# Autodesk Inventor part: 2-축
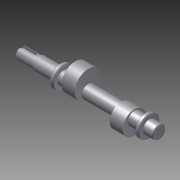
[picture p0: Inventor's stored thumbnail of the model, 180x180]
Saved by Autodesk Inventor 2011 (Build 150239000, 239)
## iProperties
Created: 2014-12
Part Number: 2-축
Document SubType Name: Modeling
Designer: user
Density: 1 g/cm^3
Author: user
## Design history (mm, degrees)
sketch "스케치1"
  geometry: L1 (-90, 0)-(90, 0); L2 (-90, 0)-(-90, 7.5); L3 (-90, 7.5)-(-66, 7.5); L4 (-66, 7.5)-(-66, 8.5); L5 (-66, 8.5)-(-39, 8.5); L6 (-39, 8.5)-(-39, 14); L7 (-39, 14)-(-34, 14); L8 (-34, 14)-(-34, 8.5); L9 (-34, 8.5)-(-27.139, 8.5); L10 (-27.139, 8.5)-(-27.139, 8.5); L11 (90, 8.5)-(90, 0); L12 (77, 8.5)-(77, 14); L13 (77, 14)-(72, 14); L14 (72, 14)-(72, 8.5); L15 (-27.139, 8.5)-(72, 8.5); L16 (77, 8.5)-(90, 8.5); 2 further points
  constraints: 32 end point, 11 parallel, 5 perpendicular, 1 coincident, 1 horizontal, 1 midpoint
  dimensions: "d0" = 180 distance of L1.start L1.end; "d1" = 15 diameter of L3 L1; "d2" = 17 diameter of L5 L1; "d3" = 28 diameter of L7 L1; "d4" = 24 distance of L2.end L3.end; "d5" = 27 distance of L4.end L5.end; "d6" = 5 distance of L6.end L7.end; "d8" = 17 diameter of L9 L1; "d9" = 17 diameter of L16 L1; "d10" = 17 diameter of L15 L1; "d11" = 28 diameter of L13 L1; "d12" = 5 distance of L12.end L13.end; "d13" = 13 distance between parallel lines of L11 L12
revolve "회전1" sketch "스케치1" stored, may be unused: angle "d14" = 90 deg
node "작업 평면1"
sketch "스케치2"
  geometry: C1 r 8.5 at (0, 0) reference; C2 r 17.5 at (-8, 0); 1 further point
  constraints: 1 centre point, 1 horizontal alignment
  dimensions: "d16" = 35 diameter of C2; "d17" = 8 distance of C2.centre point (0, 0)
extrude "돌출1" join sketch "스케치2" distance "d18" = 17; taper "d19" = 0 deg
node "작업 평면2"
sketch "스케치3"
  geometry: C1 r 8.5 at (0, 0) reference; C2 r 15 at (-5, 0); 1 further point
  constraints: 1 centre point, 1 horizontal alignment
  dimensions: "d21" = 30 diameter of C2; "d22" = 5 distance of C2.centre point (0, 0)
extrude "돌출2" join sketch "스케치3" distance "d23" = 17; taper "d24" = 0 deg
node "작업 평면3"
sketch "스케치4"
  geometry: L1 (-12, 0)-(12, 0) reference; L2 (12, -4)-(12, 0) reference; L3 (39, -4)-(12, -4) reference; L4 (39, -11.822)-(39, -4) reference; L5 (44, -11.822)-(39, -11.822) reference; L6 (44, -4)-(44, -11.822) reference; L7 (58.5, -4)-(44, -4) reference; L8 (58.5, -17.493)-(58.5, -4) reference; L9 (75.5, -17.493)-(58.5, -17.493) reference; L10 (75.5, -4)-(75.5, -17.493) reference; L11 (118.5, -4)-(75.5, -4) reference; L12 (118.5, -8.292)-(118.5, -4) reference; L13 (135.5, -8.292)-(118.5, -8.292) reference; L14 (135.5, -4)-(135.5, -8.292) reference; L15 (150, -4)-(135.5, -4) reference; L16 (150, -11.822)-(150, -4) reference; L17 (155, -11.822)-(150, -11.822) reference; L18 (155, -4)-(155, -11.822) reference; L19 (168, -4)-(155, -4) reference; L20 (168, 4)-(168, -4) reference; L21 (155, 4)-(168, 4) reference; L22 (155, 11.822)-(155, 4) reference; L23 (150, 11.822)-(155, 11.822) reference; L24 (150, 4)-(150, 11.822) reference; L25 (135.5, 4)-(150, 4) reference; L26 (135.5, 8.292)-(135.5, 4) reference; L27 (118.5, 8.292)-(135.5, 8.292) reference; L28 (118.5, 4)-(118.5, 8.292) reference; L29 (75.5, 4)-(118.5, 4) reference; L30 (75.5, 17.493)-(75.5, 4) reference; L31 (58.5, 17.493)-(75.5, 17.493) reference; L32 (58.5, 4)-(58.5, 17.493) reference; L33 (44, 4)-(58.5, 4) reference; L34 (44, 11.822)-(44, 4) reference; L35 (39, 11.822)-(44, 11.822) reference; L36 (39, 4)-(39, 11.822) reference; L37 (12, 4)-(39, 4) reference; L38 (12, 0)-(12, 4) reference; L39 (5.5, 2.5)-(-12, 2.5); L40 (-12, -7.5)-(-12, 7.5) reference; L41 (5.5, -2.5)-(-12, -2.5); A1 r 2.5 centre (5.5, 0) between (5.5, 2.5) and (5.5, -2.5); 2 further points
  constraints: 4 end point, 2 point on circle, 2 point on line, 2 tangent, 1 centre point, 1 horizontal alignment, 1 midpoint, 1 parallel, 1 perpendicular
  dimensions: "d25" = 5 diameter of A1; "d26" = 20 dimension on A1 L40
extrude "돌출3" cut sketch "스케치4" distance "d27" = 3; taper "d28" = 0 deg
chamfer "모따기1" distance "d29" = 1; stored, may be unused: second distance "d30" = 2, angle "d31" = 45 deg
node "솔리드1"
node "절단 모서리 투영1"
node "절단 모서리 투영2"
node "절단 모서리 투영3"
other parameters: "d7" = 17, "d15" = 14.5, "d20" = 14.5
